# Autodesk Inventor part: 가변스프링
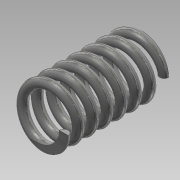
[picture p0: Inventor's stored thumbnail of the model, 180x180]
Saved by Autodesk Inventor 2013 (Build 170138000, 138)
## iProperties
Created: 2019-11
Part Number: 가변스프링
Material: 스테인리스강
Document SubType Name: Modeling
Designer: Administrator
Density: 8.08 g/cm^3
Mass: 19.7112 g
Surface Area: 33.0792 cm^2
Volume: 2.4395 cm^3
Author: Administrator
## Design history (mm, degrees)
sketch "스케치1"
  geometry: L1 (0, 0)-(8, 0); L2 (8, 0)-(8, 33.5); L3 (8, 33.5)-(0, 33.5); L4 (0, 33.5)-(0, 0); C1 r 1.5 at (8, 0)
  constraints: 8 end point, 2 parallel, 1 centre point, 1 coincident, 1 horizontal, 1 perpendicular
  dimensions: "d0" = 33.5 distance of L1.end L2.end (derived); "d2" = 3 diameter of C1; "d3" = 16 diameter of L2 L4
feature "코일1" sketch "스케치1" pitch "d4" = 10; turns "d6" = 7; dims "d5" = 33.5 (= d0), "d7" = 0, angle "d8" = 90 deg, angle "d9" = 90 deg, "d10" = 0, "d11" = 0
sketch "스케치2"
  geometry: L1 (33.5, 11)-(0, 11); L2 (0, 11)-(0, -11); L3 (0, -11)-(33.5, -11); L4 (33.5, -11)-(33.5, 11); 2 further points
  constraints: 8 end point, 2 parallel, 1 coincident, 1 horizontal, 1 midpoint, 1 perpendicular
  dimensions: "d12" = 33.5 distance of L2.end L3.end (derived); "d14" = 22 distance of L3.end L1.start
extrude "돌출1" sketch "스케치2" stored distance "d15" = 0; taper "d16" = 0 deg
node "솔리드1"
